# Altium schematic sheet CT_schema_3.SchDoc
size 410 x 272 mm
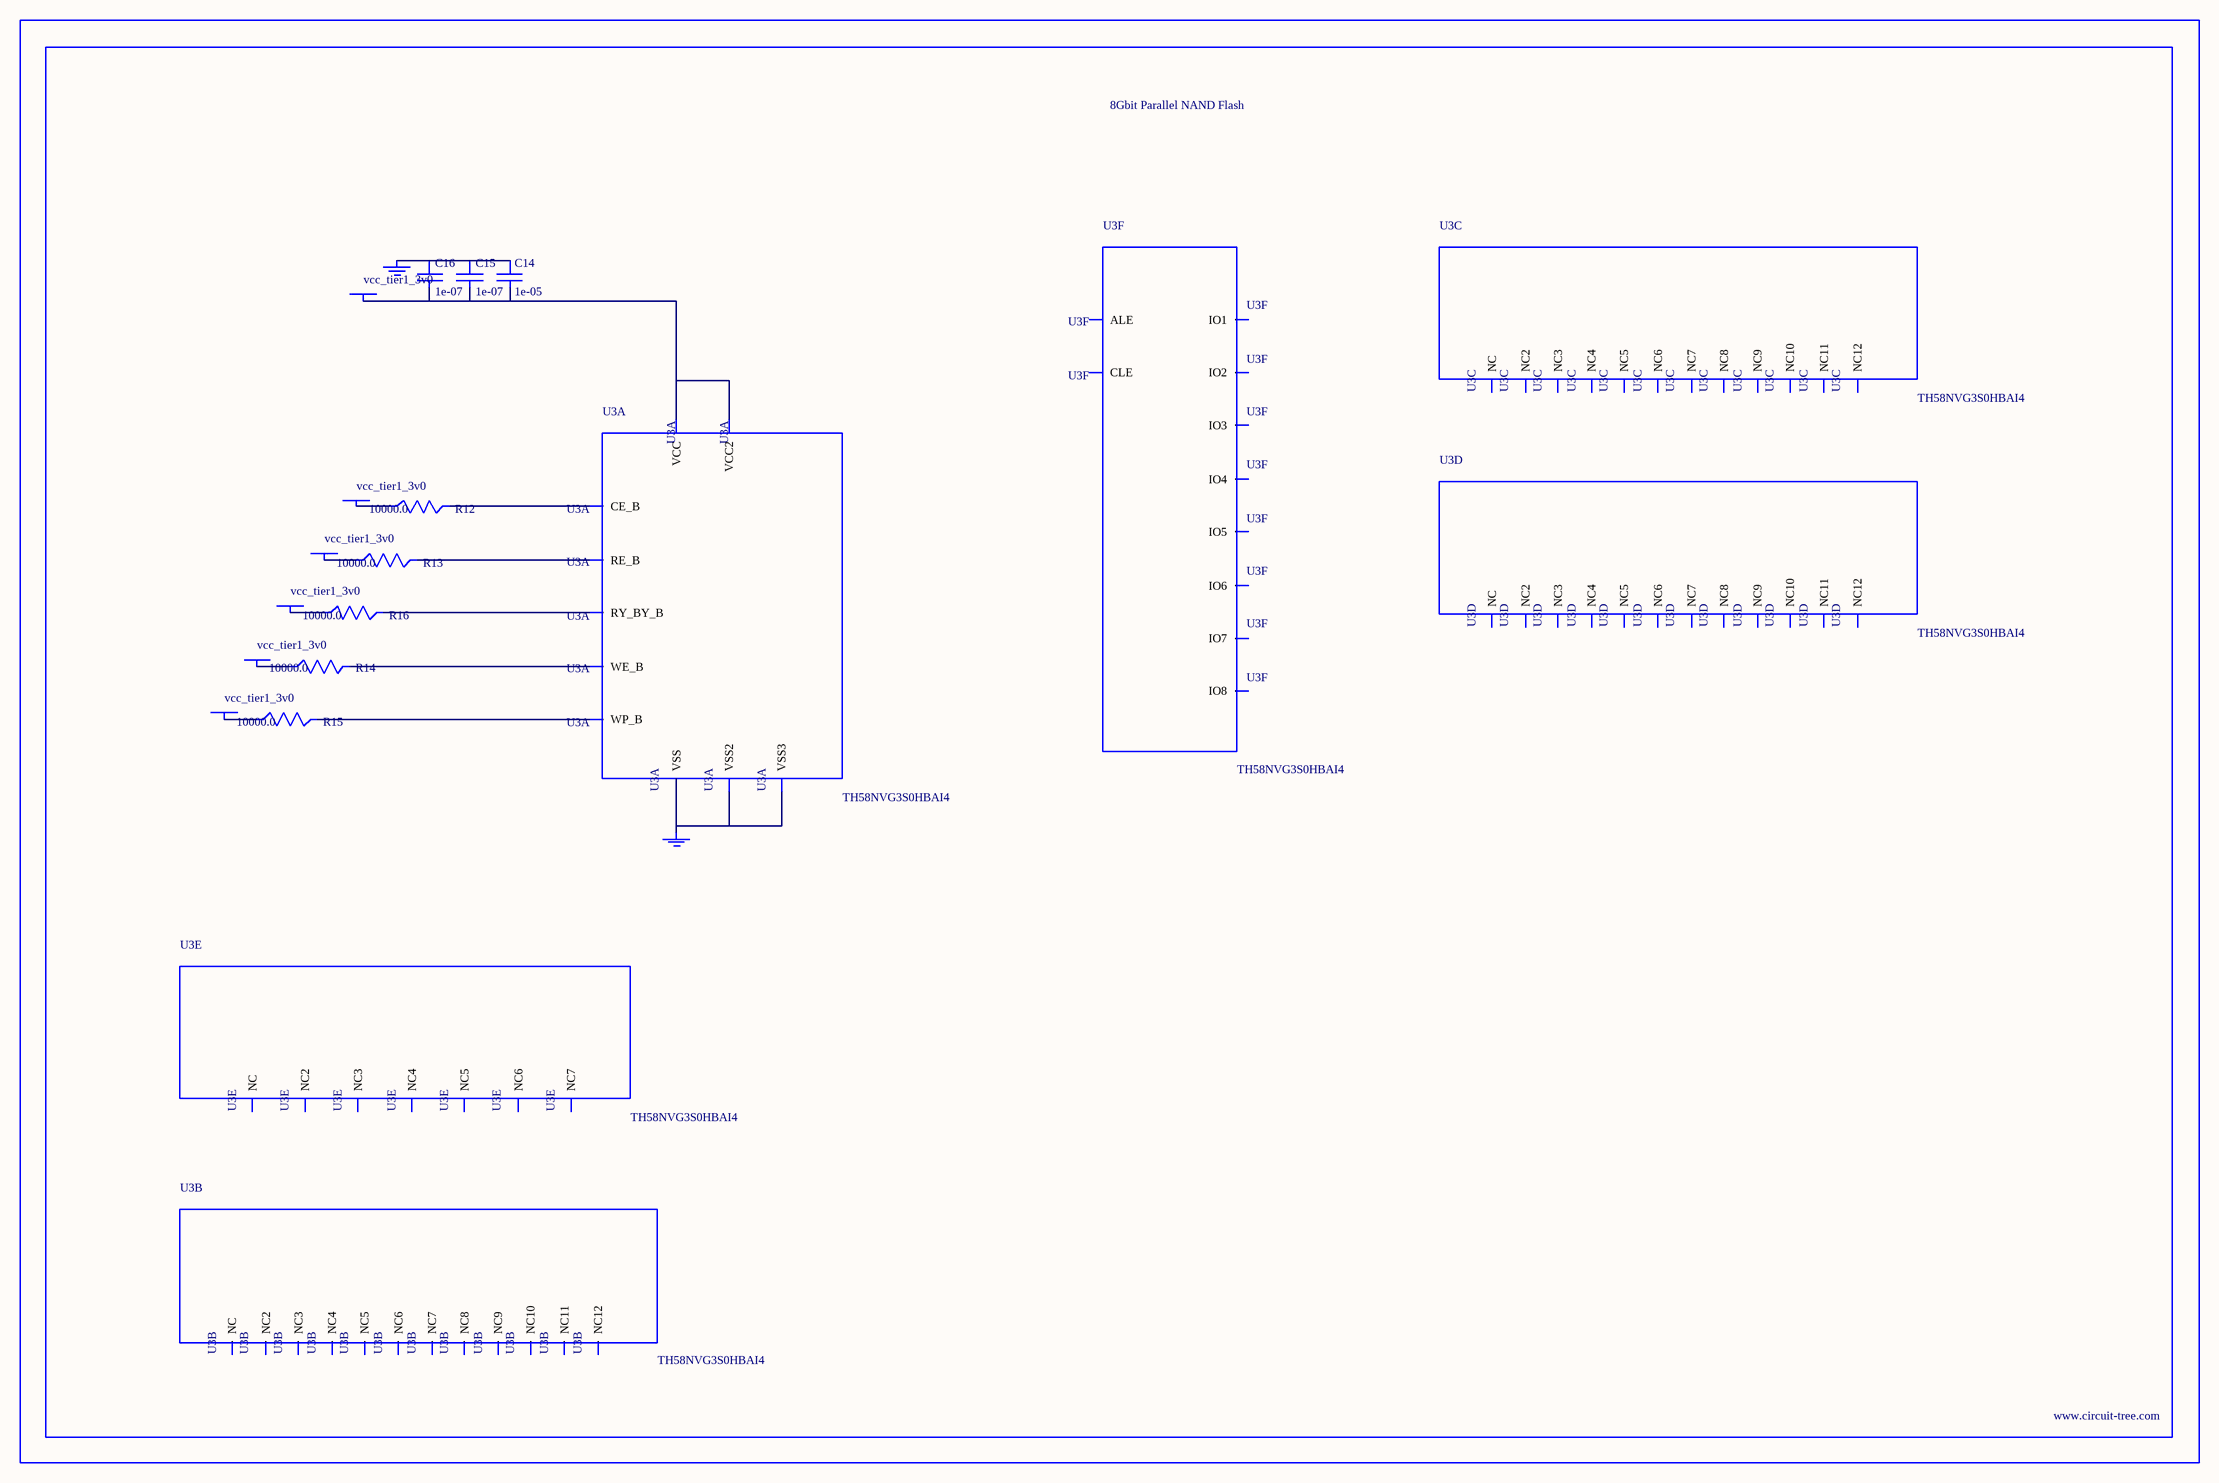
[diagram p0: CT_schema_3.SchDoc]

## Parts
BORDER2  (no value)
C14  1e-05  [C0805]
C15  1e-07  [C0402]
C16  1e-07  [C0402]
GND_INSTANCE_2_0  (no value)
GND_INSTANCE_2_1  (no value)
POWER_INSTANCE_2_0  vcc_tier1_3v0
POWER_INSTANCE_2_1  vcc_tier1_3v0
POWER_INSTANCE_2_2  vcc_tier1_3v0
POWER_INSTANCE_2_3  vcc_tier1_3v0
POWER_INSTANCE_2_4  vcc_tier1_3v0
POWER_INSTANCE_2_5  vcc_tier1_3v0
R12  10000.0  [R0603]
R13  10000.0  [R0603]
R14  10000.0  [R0603]
R15  10000.0  [R0603]
R16  10000.0  [R0603]
U3  TH58NVG3S0HBAI4  [TH58NVG3S0HBAI4]  (parts A,B,C,D,E,F of 6)

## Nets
NetC14_1: C14.1 C15.1 C16.1 GND_INSTANCE_2_0.0(GND)
NetC14_2: C14.2 C15.2 C16.2 POWER_INSTANCE_2_5.0(PWR) U3.H8(VCC) U3.J6(VCC2)
NetGND_INSTANCE_2_1_0: GND_INSTANCE_2_1.0(GND) U3.C5(VSS) U3.K3(VSS2) U3.K8(VSS3)
NetPOWER_INSTANCE_2_0_0: POWER_INSTANCE_2_0.0(PWR) R12.1
NetPOWER_INSTANCE_2_1_0: POWER_INSTANCE_2_1.0(PWR) R13.1
NetPOWER_INSTANCE_2_2_0: POWER_INSTANCE_2_2.0(PWR) R14.1
NetPOWER_INSTANCE_2_3_0: POWER_INSTANCE_2_3.0(PWR) R15.1
NetPOWER_INSTANCE_2_4_0: POWER_INSTANCE_2_4.0(PWR) R16.1
NetR12_2: R12.2 U3.C6(CE_B)
NetR13_2: R13.2 U3.D4(RE_B)
NetR14_2: R14.2 U3.C7(WE_B)
NetR15_2: R15.2 U3.C3(WP_B)
NetR16_2: R16.2 U3.C8(RY_BY_B)

Not connected (* = marked no-connect by the designer): U3 A1(NC) A2(NC3) A9(NC4) A10(NC2) B1(NC5) B9(NC7) B10(NC6) C4(ALE) D3(NC8) D5(CLE) D6(NC9) D7(NC10) D8(NC11) E3(NC12) E4(NC) E5(NC2) E6(NC3) E7(NC4) E8(NC5) F3(NC6) F4(NC7) F5(NC8) F6(NC9) F7(NC10) F8(NC11) G3(NC12) G4(NC) G5(NC2) G6(NC3) G7(NC4) G8(NC5) H3(NC6) H4(IO1) H5(NC7) H6(NC8) H7(NC9) J3(NC10) J4(IO2) J5(NC11) J7(IO6) J8(IO8) K4(IO3) K5(IO4) K6(IO5) K7(IO7) L1(NC12) L2(NC2) L9(NC3) L10(NC) M1(NC4) M2(NC6) M9(NC7) M10(NC5)

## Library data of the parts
BORDER2 = BORDER_PAGE2
C14 = C0805C106K8RACTU
C15 C16 = C0402C104K3RACTU
GND_INSTANCE_2_0 GND_INSTANCE_2_1 = GND
POWER_INSTANCE_2_0-POWER_INSTANCE_2_5 = PWR
R12-R16 = RC0603JR-0710KL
